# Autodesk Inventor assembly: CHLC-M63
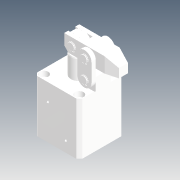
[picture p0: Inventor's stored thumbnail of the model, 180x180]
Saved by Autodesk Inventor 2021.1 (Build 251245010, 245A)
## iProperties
Created: 2019-04
Part Number: CHLC-M63
Description: STEP AP214
Document SubType Name: Assembly
Designer: user
Title: CHLC-M63.STEP
Revision Number: ÈÎºÎ
Sending System: SolidWorks 2016
Preprocessor: SwSTEP 2.0
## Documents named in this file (9)
- D:\Vault_2016\Projekty\Clamptek\Hydraulic\CHLC\CHLC-63\Inventor\CHLC-M63\CHLC-M63.iam
- D:\Vault_2016\Projekty\Clamptek\Hydraulic\CHLC\CHLC-63\Inventor\CHLC-M63\CHLC-M63-06.ipt
- D:\Vault_2016\Projekty\Clamptek\Hydraulic\CHLC\CHLC-63\Inventor\CHLC-M63\CHLC-63-05.ipt
- D:\Vault_2016\Projekty\Clamptek\Hydraulic\CHLC\CHLC-63\Inventor\CHLC-M63\CHLC-63-01.ipt
- D:\Vault_2016\Projekty\Clamptek\Hydraulic\CHLC\CHLC-63\Inventor\CHLC-M63\CHLC-63-04.ipt
- D:\Vault_2016\Projekty\Clamptek\Hydraulic\CHLC\CHLC-63\Inventor\CHLC-M63\CHLC-63-02.ipt
- D:\Vault_2016\Projekty\Clamptek\Hydraulic\CHLC\CHLC-63\Inventor\CHLC-M63\CHLC-63-03.ipt
- D:\Vault_2016\Projekty\Clamptek\Hydraulic\CHLC\CHLC-63\Inventor\CHLC-M63\CHLC-63-07.ipt
- D:\Vault_2016\Projekty\Clamptek\Hydraulic\CHLC\CHLC-63\Inventor\CHLC-M63\M6LS.ipt
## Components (16 placed, 16 different names)
1. CHLC-M63-06_1
2. CHLC-63-05_2
3. CHLC-63-01_3
4. CHLC-63-04_4
5. CHLC-63-04_5
6. CHLC-63-02_6
7. CHLC-63-03_7
8. CHLC-63-03_8
9. CHLC-63-07_9
10. CHLC-63-07_10
11. CHLC-63-07_11
12. CHLC-63-07_12
13. CHLC-63-07_13
14. CHLC-63-07_14
15. M6LS_15
16. M6LS_16
